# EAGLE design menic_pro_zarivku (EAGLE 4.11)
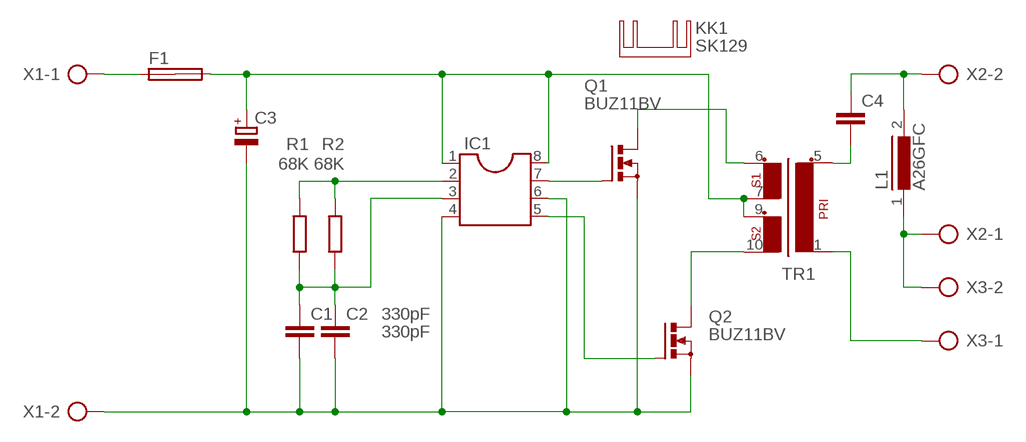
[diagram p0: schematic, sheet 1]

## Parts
C1  330pF  C-EUC025_050-024X070  [C025_050-024X070]
C2  330pF  C-EUC1210  [C1210]
C3  CPOL-EUE5-8.5  [E5-8,5]
C4  C-EU225-074X268  [C225-074X268]
F1  SHK20L  [SHK20L]
IC1  DIL8  [DIL08]
KK1  SK129  [SK129]
L1  A26GFC  [A26GFC]
Q1  BUZ11BV  [TO220BV]
Q2  BUZ11BV  [TO220BV]
R1  68K  R-EU_0207/10  [0207/10]
R2  68K  R-EU_R1210  [R1210]
TR1  EI38-2  [EI38-2]
X1  AK500/2  [AK500/2]
X2  AK500/2  [AK500/2]
X3  AK500/2  [AK500/2]

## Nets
N$1: F1.1A X1.1
N$3: C1.2 C2.2 C3.- IC1.4 IC1.6 Q1.S Q2.S X1.2
N$4: C1.1 C2.1 IC1.3 R1.1 R2.1
N$5: C4.1 L1.2 X2.2
N$6: IC1.2 R1.2 R2.2
N$9: IC1.7 Q1.G
N$10: IC1.5 Q2.G
N$11: C3.+ F1.2A IC1.1 IC1.8 Q2.D TR1.7 TR1.9 TR1.10
N$39: Q1.D TR1.6
N$42: L1.1 X2.1 X3.2
N$43: C4.2 TR1.5
N$44: TR1.1 X3.1
Unconnected: F1.1B F1.2B

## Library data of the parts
C1 C2 C4 = rcl:C-EU: CAPACITOR, European symbol
C3 = rcl:CPOL-EU: POLARIZED CAPACITOR, European symbol
F1 = fuse:SHK20L: FUSE HOLDER 5 x 20 mm, SH contact, SHH1 Schukat, E1073 Buerklin
IC1 = ic-package:DIL8: Dual In Line
KK1 = heatsink:SK129: HEATSINK
L1 = inductors:A26GFC: INDUCTOR
Q1 Q2 = transistor-power:BUZ11: N-CHANNEL MOS FET
R1 R2 = rcl:R-EU_: RESISTOR, European symbol
TR1 = trafo:EI38-2: TRANSFORMER 1 primary winding, 2 secondary windings ERA
X1-X3 = con-ptr500:AK500/2: CONNECTOR

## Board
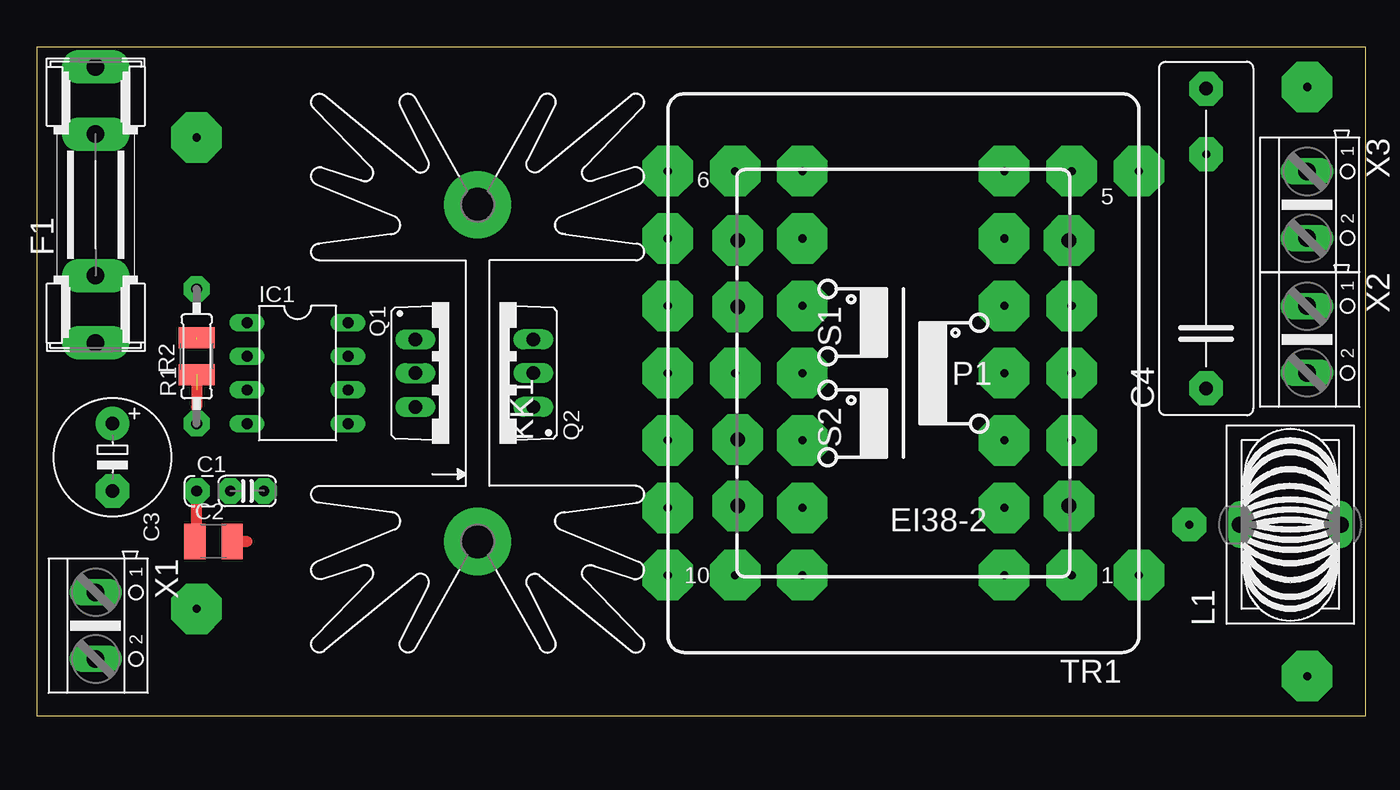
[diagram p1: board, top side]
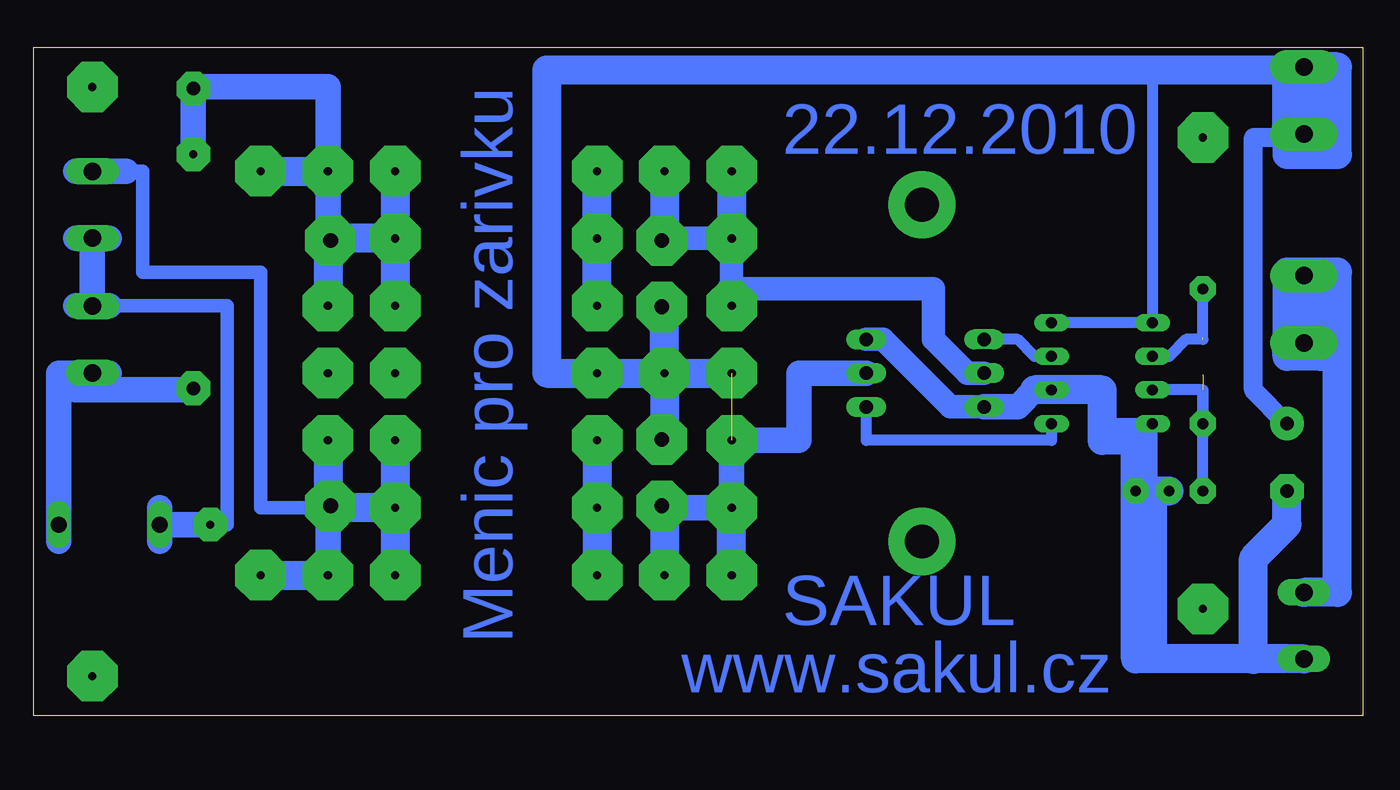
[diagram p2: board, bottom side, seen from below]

Size 100.31 x 50.47 mm. Coordinates in mm from the lower left corner, seen from the top.
Outline: 0,0 100.31,0 100.31,50.47 0,50.47 0,0
Copper layers (1*16): Top 0.035mm / dielectric 1.5mm / Bottom 0.035mm
Design rules "default": minimum track width 10mil, minimum drill 24mil, track to track 8mil, track to pad 8mil, pad to pad 8mil, via to via 8mil, smd to smd 8mil, copper to edge 40mil, drill to drill 8mil, minimum pad ring 10mil, minimum via ring 8mil, stop-mask expansion 4mil, vias tented up to drill 0mil, thermal gap 10mil

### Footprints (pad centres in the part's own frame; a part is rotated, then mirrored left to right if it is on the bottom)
C025_050-024X070 = drill 0.813 pad 1.93 octagon: 1 -3.81,0; 2 -1.27,0; 3 1.27,0
C1210 = smd 1.6 x 2.7: 1 -1.4,0; 2 1.4,0
E5-8,5 = drill 1.016 pad 2.54 round: + -2.54,0 | drill 1.016 pad 2.54 octagon: - 2.54,0
C225-074X268 = drill 1.016 pad 2.54 octagon: 1 -11.303,0; 2 11.303,0
SHK20L = drill 1.321 pad 2.54 long: 1A -10.414,0; 1B -5.334,0; 2A 10.414,0; 2B 5.334,0
DIL08 = drill 0.813 long: 1 -3.81,-3.81; 2 -1.27,-3.81; 3 1.27,-3.81; 4 3.81,-3.81; 5 3.81,3.81; 6 1.27,3.81; 7 -1.27,3.81; 8 -3.81,3.81
SK129 = drill 2.54 pad 5.08 round: A2,5 -12.7,-0.889; B2,5 12.7,-0.889
A26GFC = drill 1.194 long: 1 0,3.81; 2 0,-3.81
TO220BV = drill 1.016 long: D 0,-2.54; G -2.54,-2.54; S 2.54,-2.54
0207/10 = drill 0.813 pad 1.93 octagon: 1 -5.08,0; 2 5.08,0
R1210 = smd 1.6 x 2.7: 1 -1.4,0; 2 1.4,0
EI38-2 = drill 1.118 pad 3.81 octagon: 1 -12.497,10.008; 5 -12.497,-10.008; 6 12.497,-10.008; 7 12.497,-5.004; 9 12.497,5.004; 10 12.497,10.008
AK500/2 = drill 1.321 long: 1 -2.515,0; 2 2.515,0

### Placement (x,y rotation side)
C1  15.87,16.98 0 top
C2  13.33,13.17 0 top
C3  5.71,19.52 270 top
C4  88.26,36.03 90 top
F1  4.44,38.57 90 top
IC1  19.68,25.87 270 top
KK1  32.38,25.87 90 top
L1  94.61,14.44 90 top
Q1  31.11,25.87 270 top
Q2  34.92,25.87 90 top
R1  12.06,27.14 90 top
R2  12.06,27.14 90 top
TR1  65.4,25.87 180 top
X1  4.44,6.82 270 top
X2  95.88,28.41 270 top
X3  95.88,38.57 270 top

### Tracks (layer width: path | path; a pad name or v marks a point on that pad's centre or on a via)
N$1
  Bottom 1.93: 4.44,33.49 4.44,28.41
  Bottom 2.184: X1.1 1.9,9.34 1.9,33.49 3.17,33.49 | 5.71,28.41 5.71,33.49 4.44,33.49 3.17,33.49 | 4.44,28.41 3.17,28.41 3.17,33.49 | 3.17,33.49 3.17,27.14 5.71,27.14 5.71,28.41 | 4.44,28.41 F1.1A | 4.44,28.41 5.71,28.41
N$3  (1 unrouted)
  Top 0.813: C2.2 15.87,13.17
  Bottom 0.813: 15.87,16.98 IC1.4 19.68,22.06 19.68,24.6 IC1.6
  Bottom 1.778: Q1.S 31.11,23.33 36.19,28.41 Q2.S
  Bottom 1.93: Q1.S 26.03,23.33 24.76,24.6
  Bottom 2.184: X1.2 8.25,4.3 | 8.25,4.3 17.14,4.3 17.14,16.98 15.87,16.98 | 15.87,16.98 C1.2 | 15.87,16.98 15.87,13.17 | 15.87,13.17 15.87,5.55 | C3.- 5.71,14.44 8.25,11.9 8.25,4.3 | 8.25,4.3 8.25,4.28 | 15.87,13.17 17.14,13.17 17.14,20.79 19.68,20.79 19.68,24.6 24.76,24.6
N$4  (1 unrouted)
  Top 0.813: R2.1 12.06,23.33 | C2.1 12.06,13.17 C1.1
  Bottom 0.813: 12.06,24.6 IC1.3 | 12.06,24.6 R1.1 | C1.1 12.06,24.6
N$5
  Bottom 1.016: C4.1 95.88,24.73 X2.2 98.42,25.89 L1.2
N$6  (1 unrouted)
  Bottom 0.813: IC1.2 14.6,27.14 13.33,28.41 12.06,28.41 R1.2
N$7
  Bottom 1.93: 97.15,41.11 93.34,41.11
N$9
  Bottom 0.813: Q1.G 26.03,28.41 24.76,27.14 IC1.7
N$10
  Bottom 0.813: IC1.5 23.49,20.79 37.46,20.79 Q2.G
N$11  (via drill 0.61 pad 3.81)  (1 unrouted)
  Bottom 0.813: IC1.8 IC1.1 15.87,48.73
  Bottom 1.422: C3.+ 8.25,24.6 8.25,43.65 5.71,43.65
  Bottom 1.93: TR1.10 52.85,15.86 52.7,15.71 v47.62,15.71 v47.62,20.79 42.54,20.79 42.54,25.87 Q2.D
  Bottom 2.184: F1.2A 1.9,48.98 1.9,42.38 5.71,42.38 5.71,43.65 5.71,48.73 4.44,48.73 4.44,43.65 3.17,43.65 3.17,48.73 15.87,48.73 61.59,48.73 61.59,25.87 v57.78,25.87 v52.7,25.87 | 52.7,30.87 52.7,30.95 | 52.7,30.87 TR1.7 | v52.7,25.87 52.7,30.87 | TR1.9 52.7,20.87 v52.7,25.87 | v52.7,25.87 v47.62,25.87 | v47.62,10.63 v47.62,15.71 | 52.7,15.71 v52.7,10.63
N$14  (via drill 0.61 pad 3.81)
  other vias: 12.06,8.09
N$15  (via drill 0.61 pad 3.81)
  other vias: 12.06,43.65
N$16  (via drill 0.61 pad 3.81)
  other vias: 95.88,47.46
N$17  (via drill 0.61 pad 3.81)
  other vias: 95.88,3.01
N$22  (via drill 0.61 pad 3.81)
  other vias: 57.78,36.03
N$23  (via drill 0.61 pad 3.81)
  Bottom 2.184: v57.78,30.95 v57.78,41.11
N$24  (via drill 0.61 pad 3.81)
  Bottom 2.184: v57.78,20.79 57.78,11.9 v57.78,10.63
N$25  (via drill 0.61 pad 3.81)
  other vias: 57.78,15.71
N$28  (via drill 0.61 pad 3.81)
  other vias: 78.1,25.87
N$31  (via drill 0.61 pad 3.81)
  Bottom 2.184: v73.02,41.11 v73.02,30.95
N$34  (via drill 0.61 pad 3.81)
  other vias: 73.02,25.87
N$35  (via drill 0.61 pad 3.81)
  Bottom 2.184: v73.02,20.79 v73.02,10.63
N$39  (via drill 0.61 pad 3.81)
  Bottom 1.778: Q1.D 29.84,25.87 32.38,28.41 32.38,32.22 47.62,32.22 v47.62,36.03 52.7,36.03 52.85,35.88 TR1.6
  Bottom 2.184: v47.62,41.11 v47.62,36.03 | v52.7,41.11 52.7,36.03 | v47.62,30.95 47.62,32.22
N$41
  Bottom 1.93: 88.26,24.6 97.15,24.6 97.15,25.87 | 97.15,25.87 94.61,25.87 | 97.15,25.87 98.42,25.87 98.42,13.17
N$42  (via drill 0.61 pad 2.54)
  Bottom 1.016: X3.2 95.88,30.95 X2.1 | v86.99,14.44 85.72,14.44 85.72,30.95 94.61,30.95
  Bottom 1.93: 90.8,15.71 L1.1 | 90.8,13.17 L1.1 | 97.15,36.03 95.88,36.03 | 94.61,36.03 95.88,36.03 | 95.88,36.03 95.88,30.95 | 95.88,30.95 97.15,30.95 | 95.88,30.95 94.61,30.95 | L1.1 v86.99,14.44
N$43  (via drill 0.61 pad 2.54, 0.61 pad 3.81)
  Bottom 1.016: 78.1,47.33 C4.2 | 78.1,47.33 78.1,47.46 | 78.1,42.38 78.1,47.33 | 78.1,35.88 78.1,36.03
  Bottom 1.93: v88.26,42.38 88.26,47.46 78.1,47.46 v78.1,41.11 78.1,42.38 | TR1.5 78.1,35.88 | 78.1,36.03 78.1,39.84
  Bottom 2.184: 81.91,41.11 v83.18,41.11 v78.1,41.11 78.1,39.84 | v78.1,30.95 78.1,36.03 v73.02,36.03
N$44  (via drill 0.61 pad 3.81)
  Bottom 1.016: TR1.1 78.1,15.86 78.1,15.71 83.18,15.71 83.18,33.49 92.07,33.49 92.07,41.09 X3.1
  Bottom 1.93: 78.1,15.71 v78.1,10.63
  Bottom 2.184: v78.1,20.79 78.1,15.71 v73.02,15.71 | v83.18,10.63 79.37,10.63 v78.1,10.63

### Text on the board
Bottom: Menic pro zarivku | 22.12.2010 | SAKUL | www.sakul.cz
